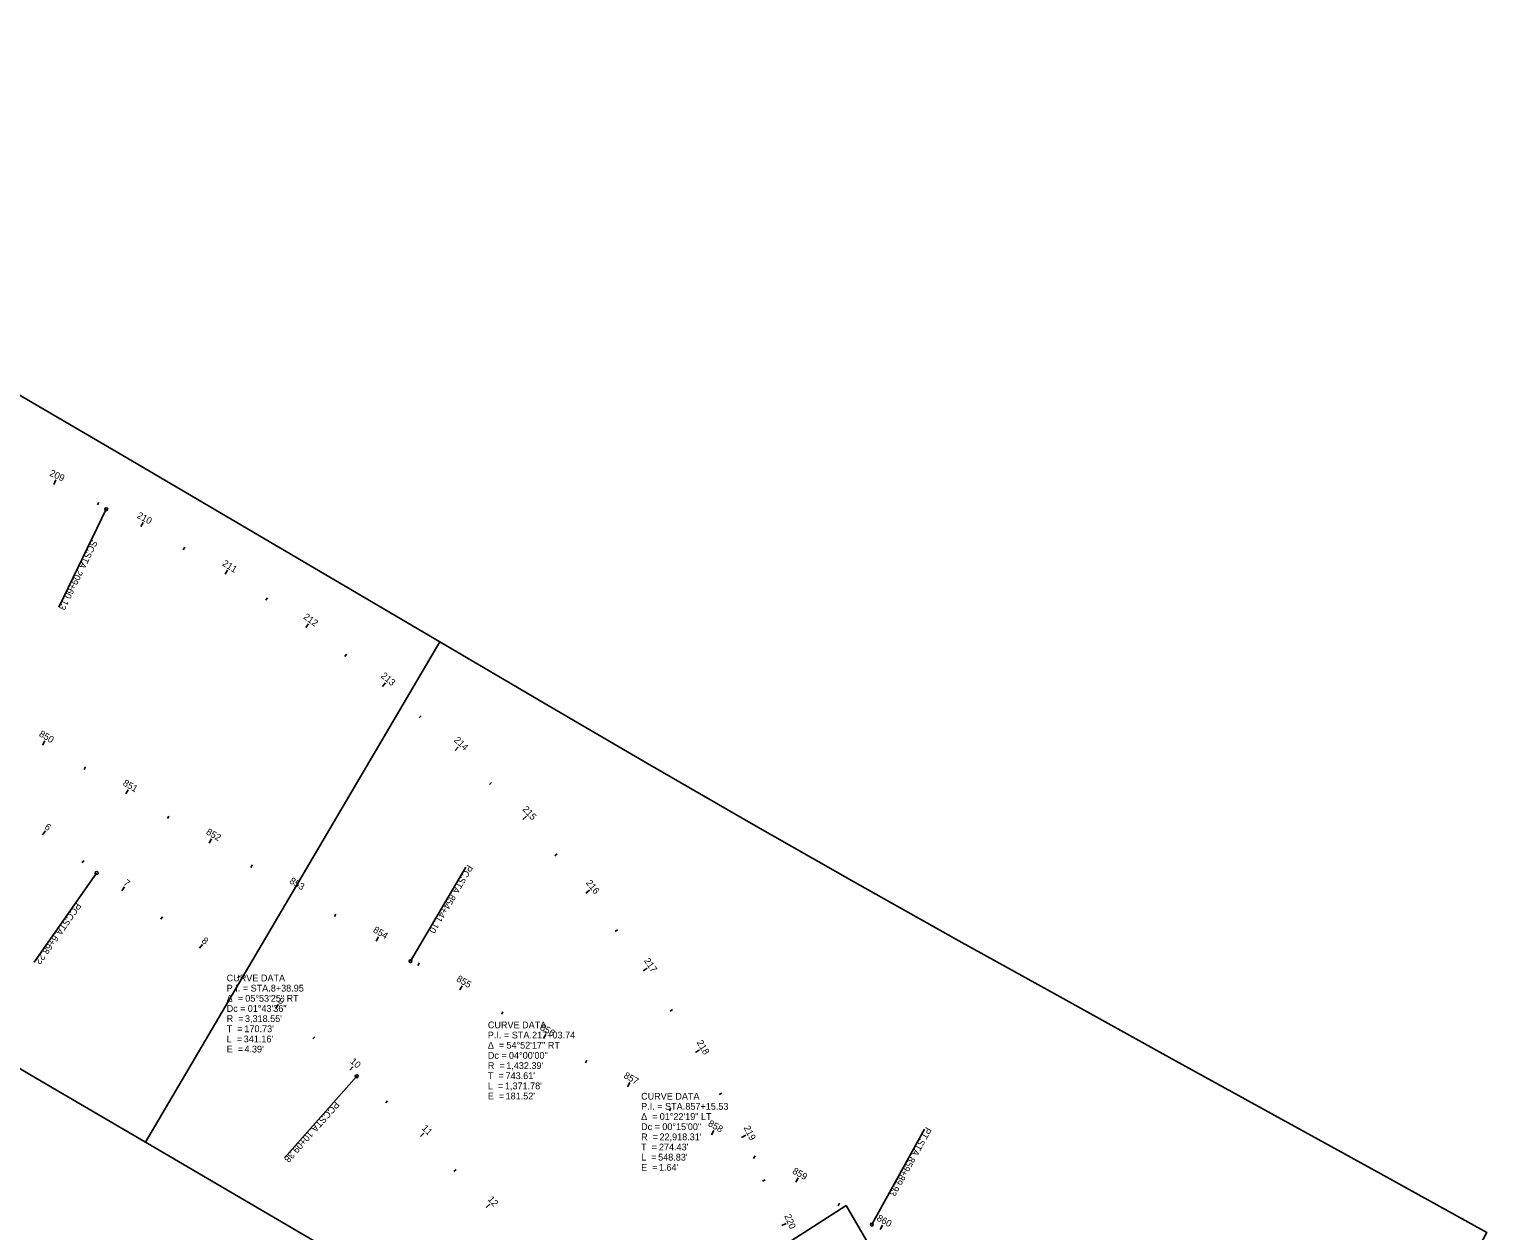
# Model space of a CAD drawing. Extents: x 75725 to 90554, y 518585 to 527848.
# Drawn here: x 86859 to 88365, y 522504 to 523746 of the extents above; entities that cross this region are included whole.
import ezdxf

# ---------------------------------------------------------------- set-up
doc = ezdxf.new("R2010")
doc.units = 0
for name, color, linetype in [('GE_P_Alignment_100_Cardinal_Points', 7, 'Continuous'), ('GE_P_Alignment_100_Curve_Data', 7, 'Continuous'), ('GE_P_Alignment_100_Stations', 7, 'Continuous'), ('SH_Named_Boundary', 7, 'Continuous')]:
    doc.layers.add(name, color=color, linetype=linetype)

msp = doc.modelspace()

# ---------------------------------------------------------------- linework, layer by layer
at = {"layer": 'GE_P_Alignment_100_Cardinal_Points'}
for p, q in [((86938.9, 523250.1), (86889.8, 523148.9)), ((87253.2, 522783.1), (87310.2, 522880.1)), ((86929, 522874.2), (86864.3, 522782.2)), ((87197.6, 522664.1), (87122.9, 522580)), ((87729.7, 522510.8), (87784, 522609.3))]:
    msp.add_line(p, q, dxfattribs=at)
for centre in [(86938.9, 523250.1), (86929, 522874.2), (87253.2, 522783.1), (87197.6, 522664.1), (87729.7, 522510.8)]:
    msp.add_circle(centre, 1.5, dxfattribs=at)
at = {"layer": 'GE_P_Alignment_100_Stations'}
for p, q in [((86884.7, 523275.9), (86886.7, 523280.5)), ((86929.9, 523254.6), (86931.2, 523257.3)), ((86974.5, 523232.2), (86976.9, 523236.6)), ((87018.5, 523208.3), (87020, 523210.9)), ((87061.6, 523182.9), (87064.2, 523187.2)), ((87103.8, 523156.1), (87105.4, 523158.6)), ((87145, 523127.8), (87147.9, 523131.9)), ((87185.2, 523098.1), (87187, 523100.4)), ((87224.3, 523066.9), (87227.5, 523070.8)), ((87262.3, 523034.5), (87264.3, 523036.7)), ((86872.9, 523006.5), (86875.4, 523010.8)), ((87299.2, 523000.7), (87302.6, 523004.3)), ((86916, 522981.2), (86917.5, 522983.8)), ((87334.9, 522965.7), (87337, 522967.8)), ((86959.1, 522955.9), (86961.6, 522960.2)), ((87002.2, 522930.5), (87003.7, 522933.1)), ((87369.3, 522929.4), (87373, 522932.8)), ((86873.2, 522913.6), (86876.1, 522917.7)), ((87045.3, 522905.2), (87047.8, 522909.5)), ((87402.4, 522892), (87404.7, 522893.9)), ((86914.1, 522884.8), (86915.9, 522887.2)), ((87088.4, 522879.9), (87089.9, 522882.5)), ((86954.9, 522855.8), (86957.8, 522859.9)), ((87131.5, 522854.6), (87134.1, 522858.9)), ((87434.2, 522853.4), (87438.2, 522856.5)), ((87174.6, 522829.2), (87176.2, 522831.8)), ((86995.3, 522826.4), (86997.1, 522828.8)), ((87217.7, 522803.9), (87220.3, 522808.2)), ((87464.7, 522813.7), (87467.1, 522815.5)), ((87035.3, 522796.4), (87038.3, 522800.3)), ((87260.9, 522778.6), (87262.4, 522781.2)), ((87493.7, 522773), (87497.8, 522775.9)), ((87074.8, 522765.7), (87076.6, 522768.1)), ((87304, 522753.3), (87306.5, 522757.7)), ((87113.8, 522734.5), (87117, 522738.4)), ((87347.2, 522728.2), (87348.7, 522730.8)), ((87521.3, 522731.4), (87523.9, 522733)), ((87152.4, 522702.7), (87154.3, 522705)), ((87390.5, 522703.1), (87393, 522707.4)), ((87433.8, 522678.1), (87435.3, 522680.7)), ((87547.5, 522688.7), (87551.8, 522691.3)), ((87190.5, 522670.3), (87193.7, 522674)), ((87477.2, 522653.2), (87479.6, 522657.6)), ((87227.6, 522636.7), (87229.6, 522638.9)), ((87572.1, 522645.2), (87574.7, 522646.7)), ((87520.6, 522628.4), (87522.1, 522631)), ((87263.4, 522601.9), (87266.9, 522605.4)), ((87564.1, 522603.7), (87566.5, 522608.1)), ((87595.2, 522600.9), (87599.7, 522603.1)), ((87607.6, 522579.1), (87609.1, 522581.8)), ((87298, 522565.8), (87300.2, 522567.8)), ((87616.7, 522555.8), (87619.5, 522557)), ((87651.2, 522554.6), (87653.6, 522559)), ((87331.3, 522528.5), (87335.1, 522531.8)), ((87694.8, 522530.2), (87696.3, 522532.9)), ((87636.7, 522509.9), (87641.3, 522511.8)), ((87738.5, 522505.9), (87740.9, 522510.3))]:
    msp.add_line(p, q, dxfattribs=at)
at = {"layer": 'SH_Named_Boundary'}
for points in [[(86205.7, 523746.4), (85901.8, 523229), (86009.6, 523165.7), (86117.4, 523102.4), (86225.1, 523039.1), (86332.9, 522975.8), (86440.7, 522912.4), (86548.5, 522849.1), (86656.3, 522785.8), (86764, 522722.5), (86871.8, 522659.2), (86979.6, 522595.9), (87283.5, 523113.2), (87175.7, 523176.5), (87068, 523239.8), (86960.2, 523303.2), (86852.4, 523366.5), (86744.6, 523429.8), (86636.8, 523493.1), (86529.1, 523556.4), (86421.3, 523619.7), (86313.5, 523683)], [(87283.5, 523113.2), (86979.6, 522595.9), (87087.4, 522532.6), (87196.5, 522468.8), (87306.2, 522405.4), (87416.2, 522342.7), (87526.6, 522280.6), (87637.3, 522219.1), (87746.8, 522158.7), (87856.2, 522098.3), (87965.6, 522037.9), (88075.1, 521977.5), (88365, 522502.8), (88255.6, 522563.2), (88146.2, 522623.6), (88036.7, 522684), (87927.3, 522744.4), (87819.5, 522804.2), (87712, 522864.7), (87604.8, 522925.8), (87498, 522987.5), (87391.3, 523049.9)], [(87703.2, 522530.7), (87240.7, 522233.1), (87293.6, 522142.3), (87338.1, 522047), (87374, 521948.2), (87401, 521846.6), (87417.8, 521745), (87427.3, 521632.4), (87432.4, 521512), (87434.8, 521389.1), (87436.3, 521261.6), (87437.9, 521134.1), (87987.9, 521141), (87986.3, 521268.4), (87984.7, 521395.9), (87982.1, 521528.9), (87976.4, 521664.6), (87964, 521809), (87938.4, 521963.7), (87898.8, 522112.8), (87846.2, 522257.7), (87780.8, 522397.4)]]:
    msp.add_lwpolyline(points, close=True, dxfattribs=at)

# ---------------------------------------------------------------- texts
at = {"layer": 'GE_P_Alignment_100_Cardinal_Points'}
for s, rotation, p in [('SC', 244.1087, (86924, 523219.1)), (' STA. ', 244.1087, (86919.3, 523209.5)), ('209+60.13', 244.1087, (86909, 523188.2)), ('PC', 239.5684, (87312.1, 522883.3)), (' STA. ', 239.5684, (87306.3, 522873.4)), ('854+41.10', 239.5684, (87294.4, 522853)), ('PCC', 234.9076, (86908, 522844.2)), (' STA. ', 234.9076, (86898.1, 522830.1)), ('6+68.22', 234.9076, (86884.5, 522810.8)), ('PCC', 228.4209, (87175.3, 522638.8)), (' STA. ', 228.4209, (87163.8, 522625.9)), ('10+09.38', 228.4209, (87148.2, 522608.3)), ('PT', 241.102, (87785.7, 522612.2)), (' STA. ', 241.102, (87780.4, 522602.5)), ('859+89.93', 241.102, (87769, 522581.8))]:
    msp.add_text(s, height=7, rotation=rotation, dxfattribs=at).set_placement(p)
at = {"layer": 'GE_P_Alignment_100_Curve_Data'}
for s, p in [('CURVE DATA', (87063.3, 522762.2)), ('P.I. = STA. ', (87063.3, 522751.7)), ('8+38.95', (87108.9, 522751.7)), ('Δ  = ', (87063.3, 522741.2)), ('05°53\'25" RT', (87082.5, 522741.2)), ('Dc = ', (87063.3, 522730.7)), ('R  = ', (87063.3, 522720.2)), ("3,318.55'", (87082.2, 522720.2)), ('01°43\'36"', (87085.1, 522730.7)), ('T  = ', (87063.3, 522709.7)), ("170.73'", (87081.6, 522709.7)), ('CURVE DATA', (87333.1, 522713.7)), ('L  = ', (87063.3, 522699.2)), ('E  = ', (87063.3, 522688.7)), ("341.16'", (87080.9, 522699.2)), ("4.39'", (87081.6, 522688.7)), ('Δ  = ', (87333.1, 522692.7)), ('P.I. = STA. ', (87333.1, 522703.2)), ('54°52\'17" RT', (87352.3, 522692.7)), ('217+03.74', (87378.8, 522703.2)), ('Dc = ', (87333.1, 522682.2)), ('04°00\'00"', (87354.9, 522682.2)), ('T  = ', (87333.1, 522661.2)), ('R  = ', (87333.1, 522671.7)), ("743.61'", (87351.4, 522661.2)), ("1,432.39'", (87352.1, 522671.7)), ('L  = ', (87333.1, 522650.7)), ("1,371.78'", (87350.7, 522650.7)), ('E  = ', (87333.1, 522640.2)), ("181.52'", (87351.4, 522640.2)), ('CURVE DATA', (87491.4, 522640)), ('P.I. = STA. ', (87491.4, 522629.5)), ('857+15.53', (87537.1, 522629.5)), ('Δ  = ', (87491.4, 522619)), ('01°22\'19" LT', (87510.6, 522619)), ('Dc = ', (87491.4, 522608.5)), ("22,918.31'", (87510.4, 522598)), ('00°15\'00"', (87513.3, 522608.5)), ('T  = ', (87491.4, 522587.5)), ('R  = ', (87491.4, 522598)), ("274.43'", (87509.8, 522587.5)), ('L  = ', (87491.4, 522577)), ("548.83'", (87509, 522577)), ('E  = ', (87491.4, 522566.5)), ("1.64'", (87509.8, 522566.5))]:
    msp.add_text(s, height=7, dxfattribs=at).set_placement(p)
at = {"layer": 'GE_P_Alignment_100_Stations'}
for s, rotation, p in [('209', 335.5817, (86879.7, 523285.1)), ('210', 332.5139, (86970, 523241.6)), ('211', 328.5138, (87058.1, 523192.4)), ('212', 324.5138, (87141.9, 523137.6)), ('213', 320.5138, (87222, 523077)), ('850', 329.5684, (86868.8, 523016.1)), ('214', 316.5138, (87297.6, 523010.9)), ('851', 329.5684, (86955.4, 522965.3)), ('215', 312.5138, (87368.3, 522939.7)), ('6', 325.0145, (86874.5, 522920.3)), ('852', 329.5684, (87041.4, 522914.8)), ('7', 324.3588, (86956.1, 522862.6)), ('853', 329.5684, (87127.6, 522864.1)), ('216', 308.5138, (87433.9, 522863.9)), ('854', 329.5684, (87213.9, 522813.5)), ('8', 322.6323, (87036.9, 522803)), ('217', 304.5138, (87494, 522783.6)), ('855', 329.7157, (87300, 522762.9)), ('9', 320.9058, (87115.7, 522741)), ('856', 329.9657, (87386.3, 522712.7)), ('218', 300.5138, (87548.6, 522699.1)), ('10', 319.1792, (87190.3, 522678.6)), ('857', 330.2157, (87472.8, 522662.9)), ('11', 314.7863, (87264.3, 522609.9)), ('858', 330.4657, (87559.9, 522613.3)), ('219', 296.5137, (87597.1, 522611.1)), ('859', 330.7157, (87647, 522564.2)), ('12', 310.7757, (87332.5, 522536.7)), ('220', 292.5137, (87639.2, 522520)), ('860', 331.102, (87734.2, 522515.5))]:
    msp.add_text(s, height=7, rotation=rotation, dxfattribs=at).set_placement(p)

doc.saveas('drawing.dxf')
